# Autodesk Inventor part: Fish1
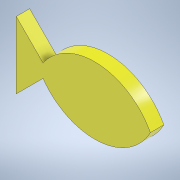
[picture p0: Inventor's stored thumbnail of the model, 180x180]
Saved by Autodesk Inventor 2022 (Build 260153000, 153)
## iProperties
Created: 2021-07
Part Number: Fish1
Material: Generic
Document SubType Name: Modeling
Designer: bluer
Density: 1 g/cm^3
Appearance: Default
Author: bluer
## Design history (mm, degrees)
sketch "Sketch1"
  geometry: L1 (0, 0)-(63.5, 0); L2 (63.5, 0)-(63.5, 31.75); L3 (63.5, 31.75)-(0, 31.75); L4 (0, 31.75)-(0, 0); L5 (12.7, 19.05)-(0, 31.75); L6 (0, 0)-(12.7, 12.7); A1 r 29.843 centre (37.128, 1.907) between (63.5, 15.875) and (12.7, 19.05); A2 r 29.843 centre (37.128, 29.843) between (12.7, 12.7) and (63.5, 15.875)
  constraints: 12 end point, 4 point on circle, 2 centre point, 2 parallel, 2 tangent, 1 horizontal, 1 midpoint, 1 perpendicular
  dimensions: "d0" = 63.5 distance of L2.end L3.end; "d1" = 31.75 distance of L1.end L2.end; "d5" = 29.845 dimension on A1 (derived); "d6" = 12.7 horizontal distance of L1.start L6.end; "d7" = 12.7 horizontal distance of L1.start L6.end; "d10" = 12.7 horizontal distance of L5.start L3.end; "d11" = 12.7 horizontal distance of L5.start L3.end; "d12" = 37.12779 distance from line of L4 A1.centre (derived); "d13" = 15.875 vertical distance of L1.start A1.start (derived)
extrude "Extrusion1" new body sketch "Sketch1" distance "d8" = 6.35; taper "d9" = 0 deg
body "Solid1"
